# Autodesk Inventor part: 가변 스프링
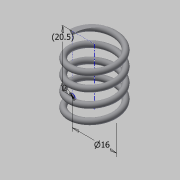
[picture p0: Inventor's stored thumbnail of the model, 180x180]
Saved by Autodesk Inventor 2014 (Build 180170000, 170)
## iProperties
Created: 2015-04
Part Number: 가변 스프링
Material: Generic
Document SubType Name: Modeling
Designer: Administrator
Density: 1 g/cm^3
Appearance: Default
Mass: 0.618653 g
Surface Area: 12.6129 cm^2
Volume: 0.618653 cm^3
Author: Administrator
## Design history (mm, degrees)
sketch "스케치4"
  geometry: L1 (0, 0)-(8, 0); L2 (8, 0)-(8, 20.5); L3 (8, 20.5)-(0, 20.5); L4 (0, 20.5)-(0, 0); C1 r 1 at (8, 0)
  constraints: 8 end point, 2 parallel, 1 centre point, 1 coincident, 1 horizontal, 1 perpendicular
  dimensions: "d0" = 16 diameter of L2 L4; "d1" = 20.49951 distance between parallel lines of L3 L1 (derived); "d2" = 2 diameter of C1
feature "코일1" pitch "d3" = 10; turns "d5" = 4; dims "d4" = 20.49951 (= d1), "d6" = 0, angle "d7" = 90 deg, angle "d8" = 90 deg, "d9" = 0, "d10" = 0
node "작업 평면1"
sketch "스케치5"
  geometry: L1 (7, 0)-(9, 0) reference; 1 further point
  constraints: 1 horizontal alignment
extrude "돌출1" cut sketch "스케치5" stored distance "d11" = 10; taper "d12" = 0 deg
node "작업 평면2"
sketch "스케치6"
  geometry: L1 (9, 0)-(7, 0) reference; 1 further point
  constraints: 1 horizontal alignment
extrude "돌출2" cut sketch "스케치6" stored distance "d13" = 10; taper "d14" = 0 deg
node "솔리드1"
node "절단 모서리 투영1"
node "절단 모서리 투영2"
